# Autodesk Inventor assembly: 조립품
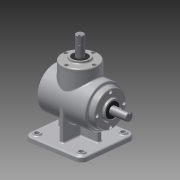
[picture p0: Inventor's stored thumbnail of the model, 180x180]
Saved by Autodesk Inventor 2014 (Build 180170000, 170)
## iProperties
Created: 2015-07
Part Number: 조립품
Document SubType Name: Assembly
Designer: user
Author: user
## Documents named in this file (14)
- C:\Users\user\Desktop\450706v1003\조립품.iam
- C:\Users\user\Desktop\450706v1003\본체.ipt
- C:\Users\user\Desktop\450706v1003\커버.ipt
- C:\Users\user\Desktop\450706v1003\M4.ipt
- C:\Users\user\Desktop\450706v1003\베어링 6203.ipt
- C:\Users\user\Desktop\450706v1003\메인 축.ipt
- 메인 축.ipt
- C:\Users\user\Desktop\450706v1003\서브 축.ipt
- 서브 축.ipt
- C:\Users\user\Desktop\450706v1003\키 4x4.ipt
- C:\Users\user\Desktop\450706v1003\키 5x5.ipt
- C:\Users\user\Desktop\450706v1003\서브 베벨기어.ipt
- C:\Users\user\Desktop\450706v1003\메인 베벨기어.ipt
- C:\Users\user\Desktop\450706v1003\오일실.ipt
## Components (8 placed, 1 different names)
1. M4:2 — Insert:6
2. M4:3
3. M4:4
4. M4:5
5. M4:1 — Insert:5
6. M4:6
7. M4:7
8. M4:8
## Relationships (2: Insert 2)
- Insert:5: M4:1
- Insert:6: M4:2
